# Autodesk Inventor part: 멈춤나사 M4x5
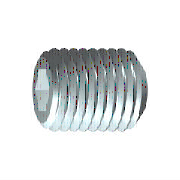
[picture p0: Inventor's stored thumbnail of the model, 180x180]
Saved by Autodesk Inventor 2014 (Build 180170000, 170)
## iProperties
IsCustomPart: 1
Created: 2012-02
Part Number: 멈춤나사 M4x5
Material: 강철, 연강
Description: 6각 소켓 머리 없는 멈춤 나사
Document SubType Name: Modeling
Standard: KS B 1028
Designer: mduedu
Standards Organization: KS
Language: ko-KR
Size Designation: 납작점M4x5
Categories: <MemberInstance><Categories><Category DisplayName="조임쇠" InternalName="e4da775c-781d-43d5-af7c-5136215cf5a6" Mnemonic="FSTN"><Category DisplayName="볼트" InternalN
Density: 1 g/cm^3
Appearance: Steel
Author: mduedu
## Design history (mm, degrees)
sketch "스케치1"
  geometry: L1 (0, 0)-(1.833, 0); L2 (5, 1.155)-(5, 2); L3 (5, 2)-(0, 2); L4 (5, 1.155)-(2.5, 1.155); L5 (2.5, 1.155)-(1.833, 0); L6 (0, -0.4)-(0, 2.4) reference; L7 (0, 2)-(0, 0)
  constraints: 13 end point, 3 parallel, 1 collinear, 1 perpendicular, 1 point on line
  dimensions: "d0" = 2.5 distance of L2.start L4.end (= INTI); "d1" = 60 deg angle of L5 L1; "d2" = 4 diameter of L3 L1 (= NND); "d3" = 2.3094 diameter of L4 L1 (= 1.1547 x SW); "d5" = 5 distance from line of L2 L3.end (= NLG)
revolve "본체" sketch "스케치1" stored, may be unused: angle "d6" = 90 deg
sketch "스케치2"
  geometry: L1 (-0.577, 1)-(0.577, 1); L2 (0.577, 1)-(1.155, 0); L3 (1.155, 0)-(0.577, -1); L4 (0.577, -1)-(-0.577, -1); L5 (-0.577, -1)-(-1.155, 0); L6 (-1.155, 0)-(-0.577, 1); A1 r 1.155 centre (0, 0) between (-0.577, 1) and (0.577, 1) reference; 2 further points
  constraints: 12 end point, 2 point on circle, 1 coincident, 1 horizontal, 11 other
extrude "슬롯" join sketch "스케치2" taper "d9" = 0 deg; stored distance "d21" = 10
workaxis "Work Axis1"
workplane "Work Plane1"
workpoint "Work Point1"
  workaxis "Work Axis4"
body "Solid1"
chamfer "모따기1" distance "d7" = 0.42941 (= -0.5 x GD1 + 0.5 x NND); stored, may be unused: angle "d8" = 45 deg (= FAWI), second distance "d29" = 0.42941 (= -0.5 x GD1 + 0.5 x NND)
feature "스레드" dims "d11" = 5 (= NLG), "d12" = 0
chamfer "모따기2" distance "d13" = 0.42941 (= -0.5 x GD1 + 0.5 x NND); stored, may be unused: angle "d14" = 45 deg (= FAWI), second distance "d30" = 0.42941 (= -0.5 x GD1 + 0.5 x NND)
other parameters: "NND" = 4 [user parameter; used in 5 equation terms], "NLG" = 5 [user parameter; used in 2 equation terms], "INTI" = 2.5 [user parameter; used in 1 equation term], "FAWI" = 45 deg [user parameter; used in 2 equation terms], "SW" = 2 [user parameter; used in 2 equation terms], "GD1" = 3.14117 (= THREADDIA - 1.2269 x PTC) [user parameter; used in 4 equation terms], "d4" = 0, "FAWI1" = 45 deg [user parameter], "d15" = 0, "d31" = 0, "GUL" = 0.42941 (= 0.61345 x PTC) [user parameter], "SPD" = 2.5 [user parameter], "TPU" = 14.28571 (computed from PTC) [user parameter], "TOA" = 30 deg [user parameter], "THREADDIA" = 4 [user parameter; used in 1 equation term], "PTC" = 0.7 [user parameter; used in 4 equation terms], "GAL" = 0.42941 (= 0.61345 x PTC) [user parameter], "E0" = 2.31 (= 1.155 x SW) [user parameter]
